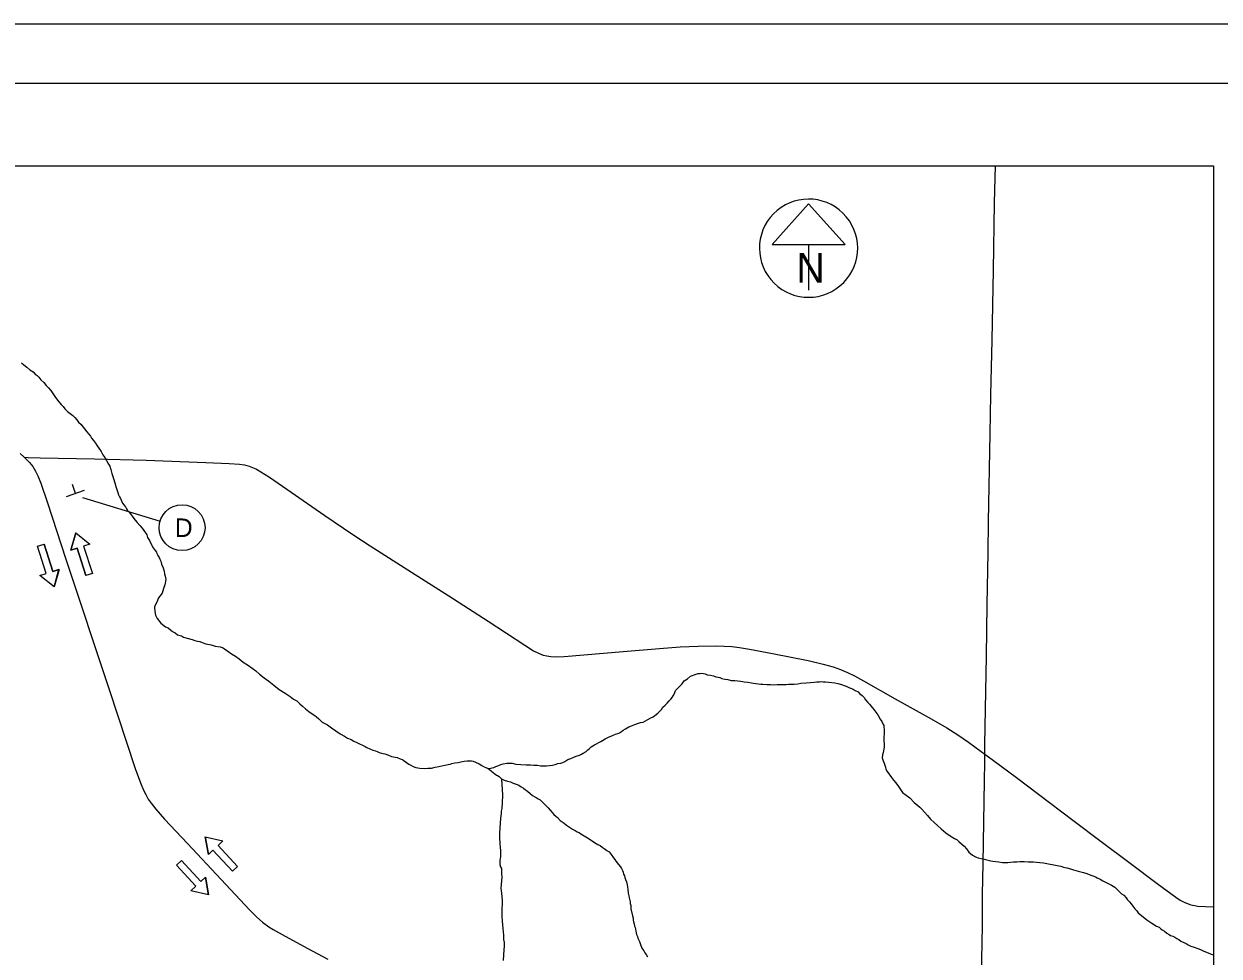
# Model space of a CAD drawing. Extents: x 1651.5 to 1685.5, y 1084.6 to 1106.6.
# Drawn here: x 1658.64 to 1668.74, y 1098.72 to 1106.6 of the extents above; entities that cross this region are included whole.
import ezdxf

# ---------------------------------------------------------------- set-up
doc = ezdxf.new("R2010")
doc.units = 0
for name, color, linetype in [('GM_X_Minor_River', 7, 'Continuous'), ('GM_X_State_Route', 7, 'Continuous'), ('GM_X_Township_Road', 7, 'Continuous'), ('SC_Scratch1', 7, 'Continuous'), ('SH_Border', 7, 'Continuous'), ('SH_Data', 7, 'Continuous'), ('SH_Text', 7, 'Continuous'), ('SN_P_Signs', 7, 'Continuous')]:
    doc.layers.add(name, color=color, linetype=linetype)

msp = doc.modelspace()

# ---------------------------------------------------------------- linework, layer by layer
at = {"layer": 'GM_X_Minor_River'}
for points in [[(1658.618, 1103.735), (1658.639, 1103.719), (1658.663, 1103.7), (1658.69, 1103.676), (1658.716, 1103.659), (1658.735, 1103.64), (1658.751, 1103.629), (1658.764, 1103.616), (1658.783, 1103.594), (1658.806, 1103.57), (1658.828, 1103.545), (1658.846, 1103.524), (1658.865, 1103.502), (1658.883, 1103.477), (1658.899, 1103.453), (1658.915, 1103.432), (1658.933, 1103.407), (1658.955, 1103.383), (1658.97, 1103.367), (1658.986, 1103.348), (1659.008, 1103.326), (1659.031, 1103.307), (1659.053, 1103.29), (1659.069, 1103.274), (1659.085, 1103.255), (1659.1, 1103.236), (1659.122, 1103.215), (1659.137, 1103.196), (1659.153, 1103.177), (1659.169, 1103.155), (1659.188, 1103.133), (1659.201, 1103.117), (1659.211, 1103.101), (1659.227, 1103.079), (1659.243, 1103.058), (1659.259, 1103.036), (1659.272, 1103.014), (1659.293, 1102.987), (1659.306, 1102.96), (1659.322, 1102.936), (1659.354, 1102.879), (1659.364, 1102.863), (1659.372, 1102.836), (1659.382, 1102.801), (1659.395, 1102.758), (1659.408, 1102.721), (1659.416, 1102.691), (1659.424, 1102.667), (1659.431, 1102.64), (1659.439, 1102.621), (1659.447, 1102.605), (1659.455, 1102.591), (1659.463, 1102.57), (1659.473, 1102.551), (1659.484, 1102.535), (1659.497, 1102.519), (1659.507, 1102.502), (1659.515, 1102.489), (1659.529, 1102.473), (1659.539, 1102.459), (1659.56, 1102.432), (1659.579, 1102.408), (1659.597, 1102.386), (1659.618, 1102.362), (1659.637, 1102.34), (1659.653, 1102.318), (1659.666, 1102.299), (1659.677, 1102.283), (1659.684, 1102.259), (1659.7, 1102.235), (1659.713, 1102.205), (1659.732, 1102.173), (1659.747, 1102.151), (1659.758, 1102.137), (1659.763, 1102.124), (1659.771, 1102.108), (1659.782, 1102.092), (1659.787, 1102.078), (1659.795, 1102.059), (1659.802, 1102.035), (1659.815, 1102.003), (1659.823, 1101.976), (1659.828, 1101.952), (1659.833, 1101.933), (1659.838, 1101.906), (1659.83, 1101.861), (1659.818, 1101.829), (1659.807, 1101.791), (1659.788, 1101.765), (1659.777, 1101.751), (1659.761, 1101.714), (1659.747, 1101.688), (1659.741, 1101.672), (1659.746, 1101.634), (1659.751, 1101.604), (1659.764, 1101.577), (1659.796, 1101.537), (1659.836, 1101.504), (1659.857, 1101.496), (1659.879, 1101.477)], [(1659.879, 1101.477), (1659.894, 1101.466), (1659.916, 1101.455), (1659.937, 1101.439), (1659.969, 1101.43), (1659.988, 1101.419), (1660.007, 1101.411), (1660.06, 1101.397), (1660.082, 1101.391), (1660.106, 1101.385), (1660.124, 1101.38), (1660.146, 1101.372), (1660.175, 1101.363), (1660.221, 1101.352), (1660.256, 1101.343), (1660.296, 1101.335), (1660.317, 1101.332), (1660.333, 1101.318), (1660.362, 1101.299), (1660.394, 1101.277), (1660.426, 1101.258), (1660.458, 1101.236), (1660.49, 1101.206), (1660.535, 1101.179), (1660.567, 1101.157), (1660.597, 1101.133), (1660.628, 1101.105), (1660.668, 1101.075), (1660.708, 1101.045), (1660.751, 1101.013), (1660.796, 1100.977), (1660.847, 1100.945), (1660.887, 1100.917), (1660.916, 1100.895), (1660.945, 1100.879), (1660.969, 1100.855), (1660.993, 1100.835), (1661.017, 1100.811), (1661.046, 1100.789), (1661.075, 1100.77), (1661.097, 1100.756), (1661.11, 1100.746), (1661.131, 1100.729), (1661.16, 1100.699), (1661.203, 1100.677), (1661.238, 1100.653), (1661.275, 1100.626), (1661.312, 1100.601), (1661.347, 1100.582), (1661.374, 1100.563), (1661.403, 1100.552), (1661.427, 1100.538), (1661.451, 1100.527), (1661.523, 1100.494), (1661.536, 1100.485), (1661.56, 1100.474), (1661.587, 1100.463), (1661.609, 1100.458), (1661.622, 1100.452), (1661.641, 1100.444), (1661.659, 1100.438), (1661.673, 1100.435), (1661.689, 1100.433), (1661.713, 1100.424), (1661.745, 1100.41), (1661.791, 1100.402), (1661.817, 1100.391), (1661.836, 1100.385), (1661.852, 1100.374), (1661.871, 1100.358), (1661.892, 1100.344), (1661.908, 1100.336), (1661.927, 1100.325), (1661.951, 1100.317), (1661.985, 1100.311), (1662.026, 1100.308), (1662.05, 1100.31), (1662.066, 1100.31), (1662.082, 1100.312), (1662.112, 1100.32), (1662.144, 1100.325), (1662.171, 1100.33), (1662.195, 1100.335), (1662.222, 1100.343), (1662.241, 1100.345), (1662.254, 1100.35), (1662.279, 1100.355), (1662.308, 1100.36), (1662.33, 1100.365), (1662.357, 1100.37), (1662.384, 1100.373), (1662.402, 1100.372), (1662.421, 1100.372), (1662.435, 1100.369), (1662.453, 1100.361), (1662.485, 1100.347), (1662.509, 1100.333), (1662.528, 1100.322), (1662.541, 1100.317), (1662.56, 1100.309), (1662.574, 1100.308)], [(1662.574, 1100.308), (1662.595, 1100.314), (1662.609, 1100.316), (1662.625, 1100.324), (1662.644, 1100.332), (1662.668, 1100.342), (1662.689, 1100.347), (1662.719, 1100.352), (1662.746, 1100.352), (1662.765, 1100.352), (1662.794, 1100.346), (1662.837, 1100.343), (1662.883, 1100.339), (1662.918, 1100.339), (1662.947, 1100.336), (1662.977, 1100.335), (1663.004, 1100.332), (1663.03, 1100.332), (1663.055, 1100.332), (1663.079, 1100.334), (1663.106, 1100.336), (1663.127, 1100.341), (1663.151, 1100.349), (1663.176, 1100.354), (1663.192, 1100.359), (1663.208, 1100.367), (1663.235, 1100.383), (1663.259, 1100.393), (1663.284, 1100.404), (1663.305, 1100.411), (1663.332, 1100.422), (1663.351, 1100.43), (1663.365, 1100.437), (1663.389, 1100.453), (1663.403, 1100.466), (1663.416, 1100.477), (1663.43, 1100.49), (1663.446, 1100.501), (1663.46, 1100.508), (1663.514, 1100.537), (1663.527, 1100.545), (1663.549, 1100.558), (1663.579, 1100.574), (1663.611, 1100.587), (1663.638, 1100.597), (1663.657, 1100.605), (1663.67, 1100.61), (1663.687, 1100.621), (1663.703, 1100.631), (1663.722, 1100.644), (1663.749, 1100.66), (1663.773, 1100.67), (1663.8, 1100.681), (1663.824, 1100.689), (1663.849, 1100.696), (1663.87, 1100.701), (1663.889, 1100.712), (1663.911, 1100.722), (1663.935, 1100.735), (1663.954, 1100.746), (1663.968, 1100.756), (1663.995, 1100.777), (1664.011, 1100.793), (1664.025, 1100.806), (1664.038, 1100.825), (1664.057, 1100.844), (1664.074, 1100.859), (1664.09, 1100.881), (1664.104, 1100.894), (1664.115, 1100.907), (1664.125, 1100.923), (1664.134, 1100.942), (1664.145, 1100.966), (1664.164, 1100.987), (1664.18, 1101.005), (1664.199, 1101.024), (1664.218, 1101.048), (1664.232, 1101.058), (1664.245, 1101.066), (1664.27, 1101.087), (1664.318, 1101.105), (1664.332, 1101.11), (1664.348, 1101.11), (1664.364, 1101.113), (1664.38, 1101.11), (1664.394, 1101.107), (1664.412, 1101.101), (1664.439, 1101.096), (1664.466, 1101.09), (1664.485, 1101.084), (1664.503, 1101.081), (1664.519, 1101.076), (1664.536, 1101.07), (1664.56, 1101.062), (1664.586, 1101.059), (1664.613, 1101.053), (1664.645, 1101.053), (1664.67, 1101.05), (1664.696, 1101.047), (1664.723, 1101.041), (1664.755, 1101.038)], [(1664.755, 1101.038), (1664.785, 1101.032), (1664.804, 1101.029), (1664.822, 1101.026), (1664.846, 1101.023), (1664.865, 1101.02), (1664.881, 1101.02), (1664.914, 1101.017), (1664.946, 1101.017), (1664.973, 1101.016), (1665.002, 1101.019), (1665.032, 1101.018), (1665.059, 1101.018), (1665.08, 1101.018), (1665.099, 1101.02), (1665.118, 1101.022), (1665.147, 1101.022), (1665.177, 1101.024), (1665.204, 1101.029), (1665.249, 1101.031), (1665.284, 1101.036), (1665.314, 1101.039), (1665.338, 1101.041), (1665.36, 1101.041), (1665.376, 1101.043), (1665.392, 1101.04), (1665.411, 1101.04), (1665.437, 1101.037), (1665.491, 1101.031), (1665.515, 1101.025), (1665.545, 1101.017), (1665.569, 1101.009), (1665.585, 1101.003), (1665.603, 1100.995), (1665.622, 1100.986), (1665.644, 1100.978), (1665.662, 1100.967), (1665.686, 1100.956), (1665.702, 1100.94), (1665.721, 1100.926), (1665.737, 1100.907), (1665.75, 1100.888), (1665.768, 1100.867), (1665.782, 1100.853), (1665.795, 1100.837), (1665.805, 1100.823), (1665.819, 1100.807), (1665.837, 1100.785), (1665.853, 1100.761), (1665.874, 1100.726), (1665.887, 1100.704), (1665.895, 1100.685), (1665.903, 1100.672), (1665.905, 1100.656), (1665.908, 1100.64), (1665.908, 1100.624), (1665.907, 1100.602), (1665.904, 1100.573), (1665.904, 1100.541), (1665.906, 1100.517), (1665.906, 1100.49), (1665.903, 1100.471), (1665.897, 1100.442), (1665.892, 1100.423), (1665.891, 1100.399), (1665.899, 1100.372), (1665.907, 1100.353), (1665.912, 1100.337), (1665.917, 1100.318), (1665.922, 1100.302), (1665.933, 1100.283), (1665.97, 1100.232), (1665.986, 1100.21), (1666.004, 1100.186), (1666.028, 1100.156), (1666.062, 1100.105), (1666.123, 1100.061), (1666.161, 1100.02), (1666.19, 1099.996), (1666.208, 1099.982), (1666.224, 1099.963), (1666.248, 1099.939), (1666.272, 1099.912), (1666.298, 1099.879), (1666.328, 1099.852), (1666.357, 1099.825), (1666.389, 1099.798), (1666.429, 1099.765), (1666.463, 1099.738), (1666.5, 1099.716), (1666.522, 1099.705), (1666.538, 1099.691), (1666.559, 1099.672), (1666.583, 1099.653), (1666.601, 1099.629), (1666.623, 1099.602), (1666.652, 1099.577), (1666.678, 1099.561), (1666.7, 1099.553), (1666.727, 1099.547), (1666.743, 1099.544)], [(1662.56, 1100.309), (1662.632, 1100.251), (1662.64, 1100.249), (1662.653, 1100.24), (1662.674, 1100.221), (1662.696, 1100.21), (1662.725, 1100.202), (1662.749, 1100.194), (1662.773, 1100.185), (1662.797, 1100.177), (1662.819, 1100.166), (1662.84, 1100.152), (1662.859, 1100.141), (1662.877, 1100.128), (1662.893, 1100.117), (1662.917, 1100.098), (1662.936, 1100.081), (1662.955, 1100.07), (1662.968, 1100.062), (1662.984, 1100.051), (1663, 1100.043), (1663.021, 1100.024), (1663.04, 1100.005), (1663.053, 1099.991), (1663.069, 1099.975), (1663.085, 1099.956), (1663.103, 1099.935), (1663.116, 1099.918), (1663.132, 1099.905), (1663.146, 1099.894), (1663.17, 1099.869), (1663.186, 1099.856), (1663.204, 1099.845), (1663.223, 1099.829), (1663.241, 1099.818), (1663.257, 1099.807), (1663.273, 1099.796), (1663.295, 1099.785), (1663.313, 1099.774), (1663.329, 1099.766), (1663.345, 1099.757), (1663.401, 1099.722), (1663.431, 1099.703), (1663.46, 1099.683), (1663.487, 1099.667), (1663.508, 1099.656), (1663.524, 1099.642), (1663.54, 1099.631), (1663.564, 1099.615), (1663.582, 1099.604), (1663.601, 1099.582), (1663.619, 1099.553), (1663.63, 1099.539), (1663.641, 1099.526), (1663.651, 1099.512), (1663.662, 1099.496), (1663.68, 1099.477), (1663.688, 1099.463), (1663.696, 1099.445), (1663.701, 1099.431), (1663.704, 1099.415), (1663.712, 1099.402), (1663.717, 1099.388), (1663.722, 1099.369), (1663.73, 1099.35), (1663.735, 1099.326), (1663.737, 1099.307), (1663.74, 1099.286), (1663.745, 1099.254), (1663.75, 1099.232), (1663.752, 1099.216), (1663.755, 1099.203), (1663.762, 1099.181), (1663.762, 1099.168), (1663.765, 1099.149), (1663.767, 1099.122), (1663.78, 1099.063), (1663.785, 1099.042), (1663.787, 1099.026), (1663.79, 1099.012), (1663.795, 1098.996), (1663.798, 1098.977), (1663.803, 1098.964), (1663.805, 1098.95), (1663.808, 1098.934), (1663.815, 1098.905), (1663.823, 1098.888), (1663.826, 1098.875), (1663.839, 1098.845), (1663.847, 1098.821), (1663.86, 1098.789), (1663.875, 1098.767), (1663.886, 1098.751), (1663.896, 1098.735), (1663.907, 1098.716)], [(1662.674, 1100.221), (1662.683, 1100.082), (1662.68, 1100.018), (1662.677, 1099.97), (1662.671, 1099.948), (1662.671, 1099.927), (1662.665, 1099.889), (1662.662, 1099.847), (1662.658, 1099.761), (1662.657, 1099.723), (1662.66, 1099.675), (1662.662, 1099.64), (1662.664, 1099.616), (1662.664, 1099.592), (1662.664, 1099.563), (1662.66, 1099.531), (1662.66, 1099.512), (1662.66, 1099.498), (1662.665, 1099.477), (1662.673, 1099.463), (1662.675, 1099.447), (1662.675, 1099.431), (1662.675, 1099.418), (1662.677, 1099.391), (1662.674, 1099.359), (1662.671, 1099.329), (1662.668, 1099.295), (1662.671, 1099.276), (1662.673, 1099.254), (1662.678, 1099.193), (1662.676, 1099.096), (1662.676, 1099.056), (1662.678, 1099.019), (1662.685, 1098.957), (1662.69, 1098.901), (1662.692, 1098.863), (1662.695, 1098.839), (1662.697, 1098.82), (1662.697, 1098.807), (1662.694, 1098.775), (1662.691, 1098.732), (1662.687, 1098.686)], [(1666.743, 1099.544), (1666.764, 1099.538), (1666.785, 1099.533), (1666.807, 1099.527), (1666.826, 1099.524), (1666.85, 1099.521), (1666.874, 1099.518), (1666.906, 1099.515), (1666.933, 1099.515), (1666.952, 1099.514), (1666.973, 1099.517), (1667, 1099.519), (1667.027, 1099.519), (1667.054, 1099.521), (1667.089, 1099.521), (1667.124, 1099.52), (1667.145, 1099.52), (1667.167, 1099.52), (1667.193, 1099.517), (1667.223, 1099.514), (1667.252, 1099.51), (1667.381, 1099.485), (1667.4, 1099.482), (1667.421, 1099.473), (1667.451, 1099.468), (1667.48, 1099.459), (1667.507, 1099.451), (1667.547, 1099.44), (1667.59, 1099.428), (1667.619, 1099.42), (1667.638, 1099.412), (1667.662, 1099.403), (1667.678, 1099.398), (1667.691, 1099.392), (1667.707, 1099.384), (1667.731, 1099.373), (1667.755, 1099.359), (1667.777, 1099.348), (1667.798, 1099.335), (1667.827, 1099.321), (1667.854, 1099.304), (1667.883, 1099.277), (1667.913, 1099.25), (1667.931, 1099.239), (1667.95, 1099.215), (1667.963, 1099.198), (1667.979, 1099.18), (1667.992, 1099.163), (1668.008, 1099.144), (1668.024, 1099.123), (1668.04, 1099.104), (1668.053, 1099.087), (1668.069, 1099.074), (1668.095, 1099.055), (1668.127, 1099.03), (1668.167, 1099), (1668.207, 1098.976), (1668.229, 1098.967), (1668.242, 1098.956), (1668.255, 1098.946), (1668.274, 1098.932), (1668.295, 1098.916), (1668.314, 1098.905), (1668.327, 1098.896), (1668.346, 1098.891), (1668.362, 1098.883), (1668.378, 1098.872), (1668.396, 1098.863), (1668.412, 1098.85), (1668.458, 1098.828), (1668.476, 1098.819), (1668.498, 1098.808), (1668.525, 1098.797), (1668.557, 1098.786), (1668.578, 1098.778), (1668.602, 1098.767), (1668.621, 1098.759), (1668.645, 1098.75), (1668.669, 1098.739), (1668.688, 1098.732)]]:
    msp.add_lwpolyline(points, dxfattribs=at)
at = {"layer": 'GM_X_State_Route'}
msp.add_lwpolyline([(1658.606, 1102.971), (1658.642, 1102.938), (1658.685, 1102.894), (1658.713, 1102.859), (1658.737, 1102.822), (1658.757, 1102.782), (1658.781, 1102.72), (1658.837, 1102.554), (1658.994, 1102.076), (1659.359, 1100.975), (1659.579, 1100.309), (1659.623, 1100.186), (1659.648, 1100.126), (1659.668, 1100.087), (1659.69, 1100.05), (1659.714, 1100.014), (1659.754, 1099.963), (1659.827, 1099.881), (1660.021, 1099.674), (1660.306, 1099.37), (1660.545, 1099.114), (1660.607, 1099.053), (1660.656, 1099.01), (1660.708, 1098.971), (1660.744, 1098.947), (1660.82, 1098.904), (1661.032, 1098.79), (1661.206, 1098.696)], dxfattribs=at)
at = {"layer": 'GM_X_Township_Road'}
for points in [[(1666.757, 1100.429), (1666.757, 1100.512), (1666.772, 1101.256), (1666.777, 1101.694), (1666.785, 1102.132), (1666.789, 1102.395), (1666.802, 1103.139), (1666.809, 1103.467), (1666.818, 1103.927), (1666.83, 1104.518), (1666.84, 1105.087), (1666.846, 1105.401)], [(1658.642, 1102.938), (1658.676, 1102.937), (1658.776, 1102.933), (1659.235, 1102.926), (1659.673, 1102.913), (1660.176, 1102.895), (1660.372, 1102.886), (1660.459, 1102.88), (1660.502, 1102.874), (1660.543, 1102.863), (1660.583, 1102.847), (1660.603, 1102.838), (1660.64, 1102.816), (1660.714, 1102.769), (1661.182, 1102.446), (1661.417, 1102.286), (1661.564, 1102.191), (1661.914, 1101.966), (1662.228, 1101.767), (1662.56, 1101.554), (1662.87, 1101.35), (1662.945, 1101.303), (1662.985, 1101.283), (1663.026, 1101.267), (1663.056, 1101.259), (1663.091, 1101.254), (1663.135, 1101.251), (1663.202, 1101.254), (1663.703, 1101.296), (1664.009, 1101.323), (1664.183, 1101.336), (1664.336, 1101.343), (1664.489, 1101.345), (1664.554, 1101.343), (1664.619, 1101.339), (1664.684, 1101.331), (1664.77, 1101.317), (1664.964, 1101.281), (1665.264, 1101.22), (1665.391, 1101.189), (1665.475, 1101.166), (1665.537, 1101.145), (1665.597, 1101.12), (1665.656, 1101.091), (1665.733, 1101.05), (1665.999, 1100.898), (1666.305, 1100.728), (1666.436, 1100.651), (1666.529, 1100.592), (1666.619, 1100.53), (1666.725, 1100.453), (1666.757, 1100.429)], [(1666.677, 1095.602), (1666.677, 1095.638), (1666.681, 1095.96), (1666.694, 1096.748), (1666.703, 1097.251), (1666.714, 1097.82), (1666.736, 1098.98), (1666.738, 1099.243), (1666.743, 1099.506), (1666.753, 1100.206), (1666.757, 1100.359), (1666.757, 1100.429)], [(1666.757, 1100.429), (1666.83, 1100.375), (1667.024, 1100.233), (1667.303, 1100.021), (1667.513, 1099.864), (1667.739, 1099.691), (1667.985, 1099.508), (1668.212, 1099.337), (1668.371, 1099.22), (1668.408, 1099.196), (1668.448, 1099.175), (1668.468, 1099.167), (1668.489, 1099.159), (1668.511, 1099.154), (1668.532, 1099.149), (1668.554, 1099.146), (1668.62, 1099.142), (1668.688, 1099.14)]]:
    msp.add_lwpolyline(points, dxfattribs=at)
at = {"layer": 'SC_Scratch1'}
msp.add_lwpolyline([(1651.463, 1106.601), (1685.463, 1106.601), (1685.463, 1084.601), (1651.463, 1084.601)], close=True, dxfattribs=at)
at = {"layer": 'SH_Border'}
msp.add_lwpolyline([(1651.963, 1106.101), (1684.963, 1106.101), (1684.963, 1085.101), (1651.963, 1085.101)], close=True, dxfattribs=at)
at = {"layer": 'SH_Data'}
for p, q in [((1665.268, 1105.079), (1664.96, 1104.737)), ((1665.576, 1104.737), (1665.268, 1105.079)), ((1664.96, 1104.737), (1665.576, 1104.737)), ((1665.268, 1104.737), (1665.268, 1104.351))]:
    msp.add_line(p, q, dxfattribs=at)
msp.add_lwpolyline([(1653.988, 1105.401), (1668.688, 1105.401), (1668.688, 1085.801), (1653.988, 1085.801)], close=True, dxfattribs=at)
msp.add_arc((1665.268, 1104.705), 0.415, 129.7798, 129.7633, dxfattribs=at)
at = {"layer": 'SH_Text'}
for p, q in [((1659.133, 1102.598), (1659.79, 1102.399)), ((1659.077, 1102.3), (1659.036, 1102.152)), ((1659.077, 1102.3), (1659.197, 1102.205)), ((1658.754, 1102.186), (1658.809, 1102.204)), ((1658.828, 1101.956), (1658.754, 1102.186)), ((1658.884, 1101.973), (1658.809, 1102.204)), ((1659.036, 1102.152), (1659.088, 1102.169)), ((1659.088, 1102.169), (1659.163, 1101.939)), ((1659.197, 1102.205), (1659.143, 1102.187)), ((1659.143, 1102.187), (1659.218, 1101.957)), ((1658.774, 1101.938), (1658.828, 1101.956)), ((1658.894, 1101.843), (1658.774, 1101.938)), ((1658.935, 1101.99), (1658.884, 1101.973)), ((1658.894, 1101.843), (1658.935, 1101.99)), ((1659.218, 1101.957), (1659.163, 1101.939)), ((1660.171, 1099.731), (1660.32, 1099.696)), ((1660.171, 1099.731), (1660.197, 1099.58)), ((1660.197, 1099.58), (1660.236, 1099.617)), ((1660.236, 1099.617), (1660.402, 1099.44)), ((1660.32, 1099.696), (1660.279, 1099.657)), ((1660.279, 1099.657), (1660.444, 1099.48)), ((1659.927, 1099.491), (1659.969, 1099.53)), ((1660.134, 1099.353), (1659.969, 1099.53)), ((1660.092, 1099.314), (1659.927, 1099.491)), ((1660.444, 1099.48), (1660.402, 1099.44)), ((1660.05, 1099.275), (1660.092, 1099.314)), ((1660.174, 1099.391), (1660.134, 1099.353)), ((1660.199, 1099.24), (1660.174, 1099.391)), ((1660.199, 1099.24), (1660.05, 1099.275))]:
    msp.add_line(p, q, dxfattribs=at)
msp.add_lwpolyline([(1658.606, 1102.971), (1658.642, 1102.938), (1658.685, 1102.894), (1658.713, 1102.859), (1658.737, 1102.822), (1658.757, 1102.782), (1658.781, 1102.72), (1658.837, 1102.554), (1658.994, 1102.076), (1659.359, 1100.975), (1659.579, 1100.309), (1659.623, 1100.186), (1659.648, 1100.126), (1659.668, 1100.087), (1659.69, 1100.05), (1659.714, 1100.014), (1659.754, 1099.963), (1659.827, 1099.881), (1660.021, 1099.674), (1660.306, 1099.37), (1660.545, 1099.114), (1660.607, 1099.053), (1660.656, 1099.01), (1660.708, 1098.971), (1660.744, 1098.947), (1660.82, 1098.904), (1661.032, 1098.79), (1661.206, 1098.696)], dxfattribs=at)
for points in [[(1659.163, 1101.939), (1659.088, 1102.169), (1659.036, 1102.152), (1659.077, 1102.3), (1659.197, 1102.205), (1659.143, 1102.187), (1659.218, 1101.957)], [(1658.809, 1102.204), (1658.884, 1101.973), (1658.936, 1101.99), (1658.894, 1101.843), (1658.774, 1101.938), (1658.828, 1101.956), (1658.754, 1102.186)], [(1660.402, 1099.44), (1660.236, 1099.617), (1660.197, 1099.58), (1660.171, 1099.731), (1660.32, 1099.696), (1660.279, 1099.657), (1660.444, 1099.48)], [(1659.969, 1099.53), (1660.134, 1099.353), (1660.174, 1099.391), (1660.199, 1099.24), (1660.05, 1099.275), (1660.092, 1099.314), (1659.927, 1099.491)]]:
    msp.add_lwpolyline(points, close=True, dxfattribs=at)
msp.add_circle((1659.975, 1102.343), 0.194, dxfattribs=at)
at = {"layer": 'SN_P_Signs'}
for p, q in [((1658.999, 1102.608), (1659.15, 1102.659)), ((1659.075, 1102.633), (1659.049, 1102.709))]:
    msp.add_line(p, q, dxfattribs=at)

# ---------------------------------------------------------------- texts
at = {"layer": 'SH_Data'}
msp.add_text('N', height=0.25, dxfattribs=at).set_placement((1665.164, 1104.414))
at = {"layer": 'SH_Text'}
msp.add_text('D', height=0.156, dxfattribs=at).set_placement((1659.914, 1102.265))

doc.saveas('drawing.dxf')
